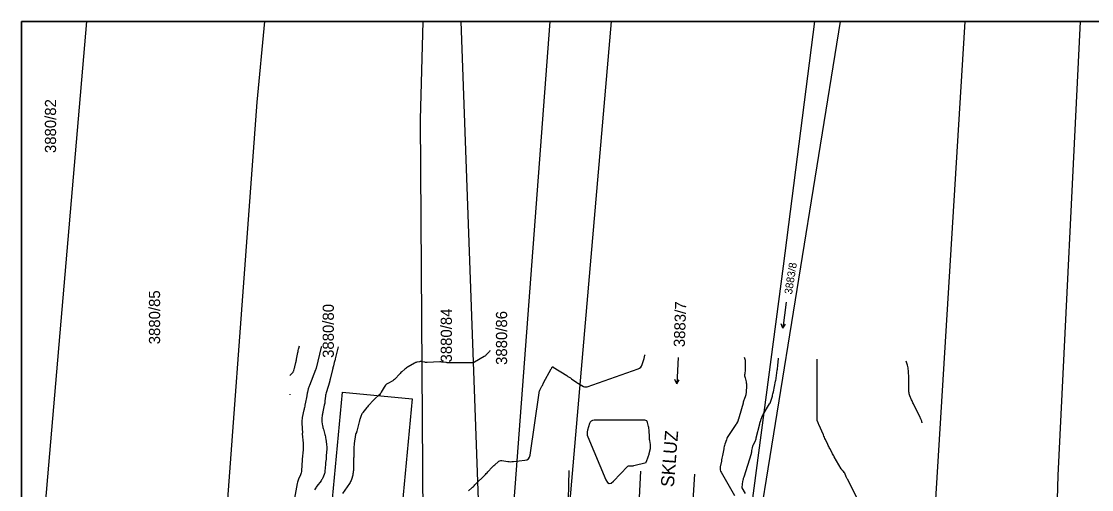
# Model space of a CAD drawing. Extents: x -534410 to -534262, y -1190162 to -1189584.
# Drawn here: x -534410.1 to -534328.7, y -1189620.1 to -1189584.5 of the extents above; entities that cross this region are included whole.
import ezdxf

# ---------------------------------------------------------------- set-up
doc = ezdxf.new("R2010")
doc.units = 0
for name, color, linetype in [('30', 7, 'Continuous'), ('31', 7, 'Continuous'), ('_N_text', 7, 'Continuous'), ('_přístup', 7, 'Continuous'), ('_rámeček', 7, 'Continuous'), ('_rámeček_mřížka', 7, 'Continuous'), ('Default', 7, 'Continuous'), ('Hranice parcel', 7, 'Continuous'), ('Parcelní čísla', 7, 'Continuous'), ('Značky kultur', 7, 'Continuous')]:
    doc.layers.add(name, color=color, linetype=linetype)

msp = doc.modelspace()

# ---------------------------------------------------------------- linework, layer by layer
at = {"layer": '30'}
for points in [[(-534389.699, -1189611.439), (-534389.49, -1189611.211), (-534389.465, -1189611.181), (-534389.443, -1189611.148), (-534389.426, -1189611.113), (-534389.412, -1189611.075), (-534389.366, -1189610.921), (-534389.354, -1189610.883), (-534389.343, -1189610.844), (-534389.333, -1189610.805), (-534389.323, -1189610.766), (-534389.245, -1189610.447), (-534389.229, -1189610.38), (-534389.214, -1189610.314), (-534389.2, -1189610.247), (-534389.187, -1189610.18), (-534389.097, -1189609.697), (-534389.079, -1189609.611), (-534389.06, -1189609.525), (-534389.039, -1189609.439), (-534389.016, -1189609.354), (-534388.967, -1189609.181)], [(-534386.02, -1189609.256), (-534386.253, -1189610.164), (-534386.27, -1189610.232), (-534386.288, -1189610.3), (-534386.305, -1189610.368), (-534386.322, -1189610.436), (-534386.389, -1189610.708), (-534386.406, -1189610.776), (-534386.423, -1189610.844), (-534386.441, -1189610.912), (-534386.458, -1189610.981), (-534386.646, -1189611.72), (-534386.65, -1189611.739), (-534386.655, -1189611.757), (-534386.658, -1189611.775), (-534386.662, -1189611.794), (-534386.675, -1189611.868), (-534386.679, -1189611.887), (-534386.683, -1189611.905), (-534386.688, -1189611.924), (-534386.693, -1189611.942), (-534386.923, -1189612.678), (-534386.947, -1189612.762), (-534386.967, -1189612.846), (-534386.982, -1189612.931), (-534386.994, -1189613.018), (-534387.032, -1189613.364), (-534387.042, -1189613.45), (-534387.055, -1189613.536), (-534387.07, -1189613.622), (-534387.088, -1189613.707), (-534387.193, -1189614.194), (-534387.207, -1189614.259), (-534387.219, -1189614.323), (-534387.229, -1189614.388), (-534387.239, -1189614.453), (-534387.273, -1189614.714), (-534387.279, -1189614.779), (-534387.28, -1189614.844), (-534387.276, -1189614.909), (-534387.267, -1189614.974), (-534387.217, -1189615.258), (-534387.204, -1189615.327), (-534387.189, -1189615.395), (-534387.172, -1189615.463), (-534387.155, -1189615.53), (-534387.046, -1189615.923), (-534387.023, -1189616.011), (-534387.003, -1189616.1), (-534386.986, -1189616.189), (-534386.971, -1189616.279), (-534386.918, -1189616.658), (-534386.907, -1189616.751), (-534386.901, -1189616.845), (-534386.9, -1189616.939), (-534386.904, -1189617.033), (-534386.935, -1189617.534), (-534386.938, -1189617.59), (-534386.943, -1189617.646), (-534386.948, -1189617.702), (-534386.954, -1189617.758), (-534386.98, -1189617.983), (-534386.986, -1189618.039), (-534386.992, -1189618.095), (-534386.997, -1189618.151), (-534387.001, -1189618.207), (-534387.035, -1189618.711), (-534387.043, -1189618.777), (-534387.055, -1189618.842), (-534387.072, -1189618.906), (-534387.095, -1189618.968), (-534387.197, -1189619.216), (-534387.224, -1189619.277), (-534387.255, -1189619.336), (-534387.289, -1189619.393), (-534387.328, -1189619.447), (-534387.649, -1189619.875), (-534387.695, -1189619.938), (-534387.738, -1189620.002), (-534387.779, -1189620.068), (-534387.818, -1189620.136)], [(-534376.121, -1189620.228), (-534375.869, -1189620.001), (-534375.806, -1189619.944), (-534375.745, -1189619.886), (-534375.684, -1189619.828), (-534375.623, -1189619.768), (-534374.819, -1189618.964), (-534374.76, -1189618.904), (-534374.701, -1189618.843), (-534374.643, -1189618.781), (-534374.586, -1189618.719), (-534374.36, -1189618.467), (-534374.302, -1189618.405), (-534374.243, -1189618.344), (-534374.183, -1189618.285), (-534374.121, -1189618.228), (-534373.869, -1189618.001), (-534373.803, -1189617.953), (-534373.733, -1189617.922), (-534373.657, -1189617.909), (-534373.576, -1189617.913), (-534373.119, -1189617.981), (-534373.015, -1189617.993), (-534372.911, -1189617.999), (-534372.806, -1189617.997), (-534372.702, -1189617.989), (-534371.838, -1189617.895), (-534371.678, -1189617.855), (-534371.557, -1189617.776), (-534371.474, -1189617.657), (-534371.429, -1189617.499), (-534370.747, -1189612.756), (-534370.735, -1189612.688), (-534370.716, -1189612.622), (-534370.692, -1189612.557), (-534370.662, -1189612.494), (-534370.53, -1189612.247), (-534370.497, -1189612.185), (-534370.464, -1189612.124), (-534370.431, -1189612.062), (-534370.398, -1189612), (-534369.825, -1189610.935), (-534369.806, -1189610.899), (-534369.778, -1189610.847), (-534369.774, -1189610.839), (-534369.749, -1189610.787), (-534369.745, -1189610.782), (-534369.741, -1189610.778), (-534369.736, -1189610.777), (-534369.73, -1189610.778), (-534369.7, -1189610.784), (-534369.693, -1189610.786), (-534369.686, -1189610.788), (-534369.679, -1189610.791), (-534369.673, -1189610.795), (-534368.641, -1189611.443), (-534368.55, -1189611.502), (-534368.459, -1189611.561), (-534368.368, -1189611.621), (-534368.279, -1189611.682), (-534367.863, -1189611.97), (-534367.803, -1189612.01), (-534367.741, -1189612.049), (-534367.679, -1189612.087), (-534367.616, -1189612.123), (-534367.361, -1189612.265), (-534367.297, -1189612.293), (-534367.231, -1189612.306), (-534367.165, -1189612.304), (-534367.096, -1189612.287), (-534363.204, -1189610.926), (-534363.098, -1189610.876), (-534363.012, -1189610.806), (-534362.946, -1189610.717), (-534362.901, -1189610.608), (-534362.76, -1189610.135), (-534362.725, -1189610.016), (-534362.691, -1189609.898), (-534362.678, -1189609.85)], [(-534355.152, -1189610.042), (-534355.122, -1189610.107), (-534355.096, -1189610.184), (-534355.08, -1189610.263), (-534355.073, -1189610.345), (-534355.065, -1189610.688), (-534355.064, -1189610.766), (-534355.066, -1189610.844), (-534355.07, -1189610.922), (-534355.076, -1189611), (-534355.106, -1189611.313), (-534355.11, -1189611.39), (-534355.107, -1189611.466), (-534355.098, -1189611.541), (-534355.081, -1189611.616), (-534355.002, -1189611.915), (-534354.986, -1189611.99), (-534354.975, -1189612.066), (-534354.97, -1189612.142), (-534354.97, -1189612.219), (-534354.993, -1189612.699), (-534355, -1189612.771), (-534355.011, -1189612.843), (-534355.027, -1189612.913), (-534355.048, -1189612.982), (-534355.144, -1189613.258), (-534355.167, -1189613.327), (-534355.189, -1189613.397), (-534355.211, -1189613.467), (-534355.231, -1189613.537), (-534355.527, -1189614.592), (-534355.534, -1189614.617), (-534355.542, -1189614.643), (-534355.549, -1189614.668), (-534355.557, -1189614.693), (-534355.597, -1189614.819), (-534355.601, -1189614.832), (-534355.605, -1189614.844), (-534355.609, -1189614.857), (-534355.614, -1189614.87), (-534355.631, -1189614.922), (-534355.636, -1189614.934), (-534355.641, -1189614.947), (-534355.647, -1189614.959), (-534355.654, -1189614.971), (-534355.717, -1189615.084), (-534355.73, -1189615.106), (-534355.744, -1189615.129), (-534355.758, -1189615.151), (-534355.773, -1189615.172), (-534356.336, -1189615.998), (-534356.384, -1189616.075), (-534356.427, -1189616.154), (-534356.464, -1189616.237), (-534356.496, -1189616.323), (-534356.61, -1189616.671), (-534356.637, -1189616.758), (-534356.661, -1189616.846), (-534356.682, -1189616.935), (-534356.701, -1189617.024), (-534356.794, -1189617.517), (-534356.815, -1189617.627), (-534356.836, -1189617.737), (-534356.857, -1189617.846), (-534356.878, -1189617.956), (-534356.964, -1189618.395), (-534356.976, -1189618.503), (-534356.968, -1189618.608), (-534356.941, -1189618.71), (-534356.895, -1189618.808), (-534355.874, -1189620.574)], [(-534346.586, -1189620.719), (-534347.292, -1189619.342), (-534347.317, -1189619.294), (-534347.34, -1189619.245), (-534347.361, -1189619.195), (-534347.382, -1189619.145), (-534347.487, -1189618.884), (-534347.496, -1189618.865), (-534347.506, -1189618.846), (-534347.518, -1189618.829), (-534347.531, -1189618.812), (-534347.586, -1189618.748), (-534347.6, -1189618.732), (-534347.615, -1189618.716), (-534347.629, -1189618.7), (-534347.644, -1189618.685), (-534347.711, -1189618.614), (-534347.726, -1189618.596), (-534347.741, -1189618.578), (-534347.754, -1189618.559), (-534347.767, -1189618.539), (-534348.289, -1189617.635), (-534348.333, -1189617.557), (-534348.377, -1189617.479), (-534348.42, -1189617.4), (-534348.462, -1189617.321), (-534348.629, -1189617.003), (-534348.671, -1189616.924), (-534348.711, -1189616.844), (-534348.751, -1189616.763), (-534348.79, -1189616.682), (-534348.96, -1189616.319), (-534349.001, -1189616.231), (-534349.041, -1189616.143), (-534349.08, -1189616.055), (-534349.119, -1189615.966), (-534349.464, -1189615.159), (-534349.478, -1189615.128), (-534349.492, -1189615.096), (-534349.506, -1189615.065), (-534349.52, -1189615.033), (-534349.575, -1189614.907), (-534349.588, -1189614.876), (-534349.596, -1189614.843), (-534349.602, -1189614.81), (-534349.603, -1189614.776), (-534349.603, -1189610.183)], [(-534389.686, -1189612.902), (-534389.675, -1189612.845)]]:
    msp.add_lwpolyline(points, dxfattribs=at)
msp.add_lwpolyline([(-534365.549, -1189619.574), (-534365.413, -1189619.657), (-534365.257, -1189619.627), (-534365.08, -1189619.486), (-534364.017, -1189618.361), (-534363.986, -1189618.334), (-534363.952, -1189618.316), (-534363.914, -1189618.306), (-534363.873, -1189618.305), (-534363.703, -1189618.317), (-534363.66, -1189618.318), (-534363.618, -1189618.316), (-534363.577, -1189618.31), (-534363.535, -1189618.3), (-534362.606, -1189618.049), (-534362.601, -1189618.047), (-534362.598, -1189618.044), (-534362.595, -1189618.039), (-534362.593, -1189618.034), (-534362.59, -1189618.011), (-534362.589, -1189618.005), (-534362.588, -1189618), (-534362.586, -1189617.994), (-534362.584, -1189617.989), (-534362.442, -1189617.621), (-534362.419, -1189617.557), (-534362.398, -1189617.493), (-534362.379, -1189617.428), (-534362.363, -1189617.363), (-534362.28, -1189616.994), (-534362.267, -1189616.919), (-534362.261, -1189616.844), (-534362.263, -1189616.769), (-534362.272, -1189616.693), (-534362.323, -1189616.39), (-534362.335, -1189616.314), (-534362.344, -1189616.238), (-534362.351, -1189616.162), (-534362.355, -1189616.085), (-534362.373, -1189615.644), (-534362.378, -1189615.563), (-534362.387, -1189615.482), (-534362.4, -1189615.402), (-534362.417, -1189615.322), (-534362.491, -1189615.004), (-534362.517, -1189614.934), (-534362.56, -1189614.884), (-534362.618, -1189614.854), (-534362.691, -1189614.845), (-534366.559, -1189614.845), (-534366.68, -1189614.86), (-534366.777, -1189614.908), (-534366.851, -1189614.986), (-534366.902, -1189615.097), (-534367.06, -1189615.601), (-534367.088, -1189615.727), (-534367.093, -1189615.851), (-534367.076, -1189615.975), (-534367.036, -1189616.097), (-534365.664, -1189619.379)], close=True, dxfattribs=at)
at = {"layer": '31'}
for points in [[(-534387.304, -1189609.223), (-534387.316, -1189609.271), (-534387.329, -1189609.325), (-534387.342, -1189609.378), (-534387.681, -1189610.772), (-534387.689, -1189610.801), (-534387.7, -1189610.849), (-534387.706, -1189610.871), (-534387.708, -1189610.879), (-534387.711, -1189610.888), (-534387.739, -1189610.959), (-534387.752, -1189610.993), (-534388.222, -1189612.19), (-534388.245, -1189612.254), (-534388.267, -1189612.318), (-534388.286, -1189612.383), (-534388.302, -1189612.448), (-534388.364, -1189612.712), (-534388.379, -1189612.779), (-534388.394, -1189612.845), (-534388.408, -1189612.911), (-534388.422, -1189612.977), (-534388.544, -1189613.584), (-534388.552, -1189613.623), (-534388.559, -1189613.662), (-534388.567, -1189613.701), (-534388.573, -1189613.74), (-534388.6, -1189613.896), (-534388.607, -1189613.936), (-534388.614, -1189613.975), (-534388.622, -1189614.013), (-534388.63, -1189614.052), (-534388.756, -1189614.627), (-534388.777, -1189614.736), (-534388.789, -1189614.846), (-534388.795, -1189614.956), (-534388.793, -1189615.067), (-534388.755, -1189615.826), (-534388.755, -1189615.833), (-534388.756, -1189615.84), (-534388.758, -1189615.854), (-534388.759, -1189615.861), (-534388.759, -1189615.867), (-534388.701, -1189616.599), (-534388.694, -1189616.722), (-534388.692, -1189616.844), (-534388.694, -1189616.967), (-534388.702, -1189617.09), (-534388.76, -1189617.818), (-534388.76, -1189617.827), (-534388.761, -1189617.836), (-534388.761, -1189617.858), (-534388.761, -1189617.871), (-534388.816, -1189618.671), (-534388.826, -1189618.757), (-534388.843, -1189618.841), (-534388.866, -1189618.923), (-534388.897, -1189619.004), (-534389.035, -1189619.324), (-534389.068, -1189619.404), (-534389.095, -1189619.486), (-534389.119, -1189619.569), (-534389.138, -1189619.654), (-534389.357, -1189620.769)], [(-534374.468, -1189609.55), (-534374.482, -1189609.568), (-534374.514, -1189609.607), (-534374.547, -1189609.645), (-534374.581, -1189609.682), (-534374.616, -1189609.718), (-534374.759, -1189609.86), (-534374.796, -1189609.895), (-534374.834, -1189609.927), (-534374.875, -1189609.956), (-534374.917, -1189609.983), (-534375.663, -1189610.429), (-534375.704, -1189610.449), (-534375.746, -1189610.464), (-534375.791, -1189610.473), (-534375.837, -1189610.475), (-534376.024, -1189610.471), (-534376.071, -1189610.47), (-534376.118, -1189610.47), (-534376.165, -1189610.469), (-534376.212, -1189610.469), (-534377.274, -1189610.469), (-534377.321, -1189610.469), (-534377.368, -1189610.469), (-534377.415, -1189610.468), (-534377.462, -1189610.467), (-534377.649, -1189610.464), (-534377.696, -1189610.462), (-534377.743, -1189610.459), (-534377.789, -1189610.454), (-534377.836, -1189610.449), (-534378.078, -1189610.414), (-534378.133, -1189610.408), (-534378.189, -1189610.404), (-534378.245, -1189610.402), (-534378.301, -1189610.404), (-534379.247, -1189610.445), (-534379.297, -1189610.446), (-534379.348, -1189610.443), (-534379.397, -1189610.437), (-534379.447, -1189610.428), (-534379.644, -1189610.384), (-534379.694, -1189610.376), (-534379.743, -1189610.374), (-534379.792, -1189610.376), (-534379.842, -1189610.385), (-534380.039, -1189610.428), (-534380.088, -1189610.441), (-534380.135, -1189610.457), (-534380.181, -1189610.477), (-534380.225, -1189610.5), (-534380.693, -1189610.765), (-534380.761, -1189610.806), (-534380.828, -1189610.851), (-534380.892, -1189610.9), (-534380.953, -1189610.952), (-534381.194, -1189611.166), (-534381.253, -1189611.22), (-534381.311, -1189611.277), (-534381.367, -1189611.334), (-534381.422, -1189611.394), (-534381.636, -1189611.635), (-534381.692, -1189611.692), (-534381.751, -1189611.745), (-534381.815, -1189611.792), (-534381.883, -1189611.835), (-534382.263, -1189612.052), (-534382.345, -1189612.106), (-534382.418, -1189612.17), (-534382.482, -1189612.242), (-534382.536, -1189612.324), (-534382.753, -1189612.704), (-534382.795, -1189612.772), (-534382.843, -1189612.836), (-534382.895, -1189612.896), (-534382.953, -1189612.952), (-534383.194, -1189613.166), (-534383.253, -1189613.22), (-534383.311, -1189613.277), (-534383.367, -1189613.334), (-534383.422, -1189613.394), (-534383.636, -1189613.635), (-534383.689, -1189613.695), (-534383.742, -1189613.756), (-534383.793, -1189613.818), (-534383.844, -1189613.881), (-534384.149, -1189614.258), (-534384.187, -1189614.309), (-534384.22, -1189614.364), (-534384.248, -1189614.42), (-534384.272, -1189614.48), (-534384.356, -1189614.723), (-534384.377, -1189614.784), (-534384.396, -1189614.845), (-534384.414, -1189614.907), (-534384.431, -1189614.969), (-534384.614, -1189615.683), (-534384.62, -1189615.705), (-534384.627, -1189615.726), (-534384.635, -1189615.746), (-534384.644, -1189615.766), (-534384.682, -1189615.846), (-534384.691, -1189615.867), (-534384.698, -1189615.887), (-534384.703, -1189615.909), (-534384.707, -1189615.93), (-534384.804, -1189616.624), (-534384.818, -1189616.734), (-534384.828, -1189616.845), (-534384.835, -1189616.956), (-534384.839, -1189617.067), (-534384.85, -1189617.68), (-534384.851, -1189617.708), (-534384.852, -1189617.736), (-534384.852, -1189617.764), (-534384.853, -1189617.792), (-534384.858, -1189617.905), (-534384.858, -1189617.933), (-534384.859, -1189617.961), (-534384.86, -1189617.989), (-534384.861, -1189618.017), (-534384.873, -1189618.669), (-534384.877, -1189618.756), (-534384.887, -1189618.843), (-534384.903, -1189618.929), (-534384.924, -1189619.013), (-534385.019, -1189619.351), (-534385.047, -1189619.434), (-534385.08, -1189619.514), (-534385.12, -1189619.591), (-534385.167, -1189619.665), (-534385.692, -1189620.431)], [(-534355.038, -1189620.419), (-534355.285, -1189619.991), (-534355.296, -1189619.968), (-534355.303, -1189619.943), (-534355.305, -1189619.917), (-534355.302, -1189619.891), (-534355.281, -1189619.785), (-534355.276, -1189619.758), (-534355.271, -1189619.732), (-534355.266, -1189619.705), (-534355.262, -1189619.678), (-534355.211, -1189619.379), (-534355.2, -1189619.321), (-534355.187, -1189619.263), (-534355.172, -1189619.205), (-534355.155, -1189619.148), (-534354.596, -1189617.363), (-534354.581, -1189617.313), (-534354.569, -1189617.261), (-534354.558, -1189617.21), (-534354.549, -1189617.158), (-534354.516, -1189616.949), (-534354.506, -1189616.897), (-534354.493, -1189616.847), (-534354.476, -1189616.797), (-534354.455, -1189616.749), (-534354.316, -1189616.461), (-534354.287, -1189616.396), (-534354.262, -1189616.331), (-534354.24, -1189616.264), (-534354.222, -1189616.195), (-534353.962, -1189615.104), (-534353.955, -1189615.077), (-534353.948, -1189615.051), (-534353.94, -1189615.025), (-534353.932, -1189614.999), (-534353.887, -1189614.87), (-534353.883, -1189614.857), (-534353.878, -1189614.844), (-534353.874, -1189614.832), (-534353.87, -1189614.819), (-534353.854, -1189614.767), (-534353.85, -1189614.755), (-534353.846, -1189614.742), (-534353.841, -1189614.729), (-534353.836, -1189614.717), (-534353.769, -1189614.538), (-534353.755, -1189614.504), (-534353.74, -1189614.471), (-534353.723, -1189614.439), (-534353.705, -1189614.408), (-534353.208, -1189613.6), (-534353.169, -1189613.531), (-534353.134, -1189613.459), (-534353.106, -1189613.385), (-534353.082, -1189613.309), (-534352.999, -1189612.999), (-534352.978, -1189612.922), (-534352.959, -1189612.844), (-534352.941, -1189612.766), (-534352.925, -1189612.687), (-534352.756, -1189611.86), (-534352.753, -1189611.852), (-534352.75, -1189611.841), (-534352.748, -1189611.834), (-534352.624, -1189611.039), (-534352.61, -1189610.942), (-534352.597, -1189610.844), (-534352.586, -1189610.746), (-534352.577, -1189610.648), (-534352.537, -1189610.169), (-534352.533, -1189610.114), (-534352.533, -1189610.108)], [(-534341.595, -1189615.04), (-534341.609, -1189615.004), (-534341.617, -1189614.983), (-534341.625, -1189614.961), (-534341.633, -1189614.94), (-534341.641, -1189614.918), (-534341.675, -1189614.818), (-534341.681, -1189614.803), (-534341.687, -1189614.787), (-534341.693, -1189614.772), (-534341.7, -1189614.757), (-534341.736, -1189614.683), (-534341.758, -1189614.638), (-534342.267, -1189613.586), (-534342.302, -1189613.513), (-534342.337, -1189613.439), (-534342.371, -1189613.365), (-534342.404, -1189613.291), (-534342.536, -1189612.993), (-534342.566, -1189612.918), (-534342.587, -1189612.841), (-534342.601, -1189612.762), (-534342.607, -1189612.682), (-534342.628, -1189612.015), (-534342.629, -1189611.986), (-534342.629, -1189611.958), (-534342.629, -1189611.93), (-534342.63, -1189611.901), (-534342.63, -1189611.788), (-534342.63, -1189611.759), (-534342.63, -1189611.731), (-534342.631, -1189611.703), (-534342.631, -1189611.674), (-534342.651, -1189611.061), (-534342.658, -1189610.953), (-534342.672, -1189610.847), (-534342.694, -1189610.742), (-534342.722, -1189610.637), (-534342.81, -1189610.356)]]:
    msp.add_lwpolyline(points, dxfattribs=at)
at = {"layer": '_přístup'}
msp.add_lwpolyline([(-534387.143, -1189628.143), (-534385.688, -1189612.702), (-534380.389, -1189613.202), (-534381.845, -1189628.642)], close=True, dxfattribs=at)
at = {"layer": '_rámeček'}
for p, q in [((-534410.126, -1189584.47), (-534410.126, -1190161.97)), ((-534261.626, -1189584.47), (-534410.126, -1189584.47))]:
    msp.add_line(p, q, dxfattribs=at)
msp.add_lwpolyline([(-534410.126, -1189584.47), (-534261.626, -1189584.47), (-534261.626, -1189689.47), (-534410.126, -1189689.47)], close=True, dxfattribs=at)
at = {"layer": '_rámeček_mřížka'}
for p, q in [((-534410.126, -1189584.47), (-534410.126, -1190161.97)), ((-534261.626, -1189584.47), (-534410.126, -1189584.47))]:
    msp.add_line(p, q, dxfattribs=at)
at = {"layer": 'Default'}
for p, q in [((-534368.495, -1189618.669), (-534368.65, -1189626.81)), ((-534363.102, -1189620.721), (-534363.002, -1189618.721)), ((-534359.012, -1189620.961), (-534358.886, -1189618.961))]:
    msp.add_line(p, q, dxfattribs=at)
at = {"layer": 'Hranice parcel'}
for points in [[(-534408.99, -1189627.6), (-534408.6, -1189624.8), (-534405.151, -1189584.47)], [(-534391.623, -1189584.47), (-534392.21, -1189590.63), (-534395.28, -1189632.21)], [(-534379.46, -1189637.54), (-534379.76, -1189591.95), (-534379.572, -1189584.47)], [(-534374.7, -1189639.14), (-534376.664, -1189584.47)], [(-534369.94, -1189584.47), (-534373, -1189625.37), (-534374.52, -1189639.2)], [(-534368.76, -1189625.38), (-534365.237, -1189584.47)], [(-534356.61, -1189636.93), (-534352.14, -1189603.1), (-534349.757, -1189584.47)], [(-534347.83, -1189584.47), (-534354.43, -1189625.3), (-534356.61, -1189636.93)], [(-534347.07, -1189935.15), (-534347.12, -1189900.1), (-534346.3, -1189826.77), (-534344.77, -1189736.43), (-534342.85, -1189658.07), (-534338.334, -1189584.47)], [(-534338.84, -1189942.48), (-534336.49, -1189881.83), (-534334.78, -1189743.85), (-534331.25, -1189619.05), (-534329.563, -1189584.47)]]:
    msp.add_lwpolyline(points, dxfattribs=at)
at = {"layer": 'Značky kultur'}
for p, q in [((-534351.951, -1189605.848), (-534352.196, -1189607.843)), ((-534352.196, -1189607.843), (-534352.323, -1189607.498)), ((-534352.196, -1189607.843), (-534351.99, -1189607.539)), ((-534360.157, -1189610.065), (-534360.263, -1189612.072)), ((-534360.263, -1189612.072), (-534360.413, -1189611.737)), ((-534360.263, -1189612.072), (-534360.078, -1189611.754))]:
    msp.add_line(p, q, dxfattribs=at)

# ---------------------------------------------------------------- texts
at = {"layer": '_N_text'}
msp.add_text('SKLUZ', height=1, rotation=85.46265, dxfattribs=at).set_placement((-534360.496, -1189619.962))
at = {"layer": 'Parcelní čísla'}
for s, height, rotation, p in [('3880/82', 0.85, 90, (-534407.488, -1189594.499)), ('3883/8', 0.595, 81, (-534351.509, -1189605.288)), ('3880/85', 0.85, 90, (-534399.574, -1189609.061)), ('3880/80', 0.85, 90, (-534386.359, -1189610.098)), ('3883/7', 0.85, 88, (-534359.665, -1189609.289)), ('3880/84', 0.85, 90, (-534377.379, -1189610.445)), ('3880/86', 0.85, 90, (-534373.177, -1189610.633))]:
    msp.add_text(s, height=height, rotation=rotation, dxfattribs=at).set_placement(p)

doc.saveas('drawing.dxf')
